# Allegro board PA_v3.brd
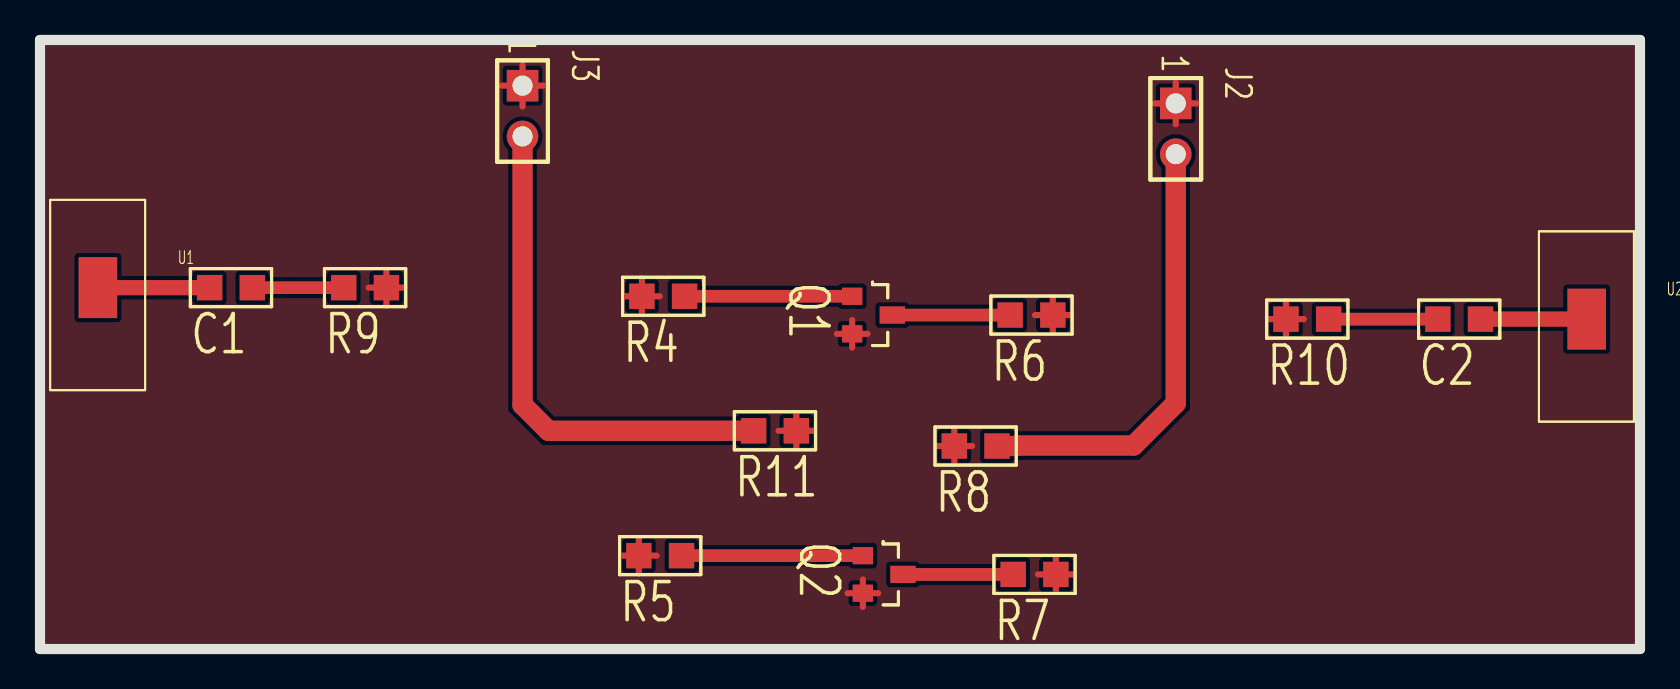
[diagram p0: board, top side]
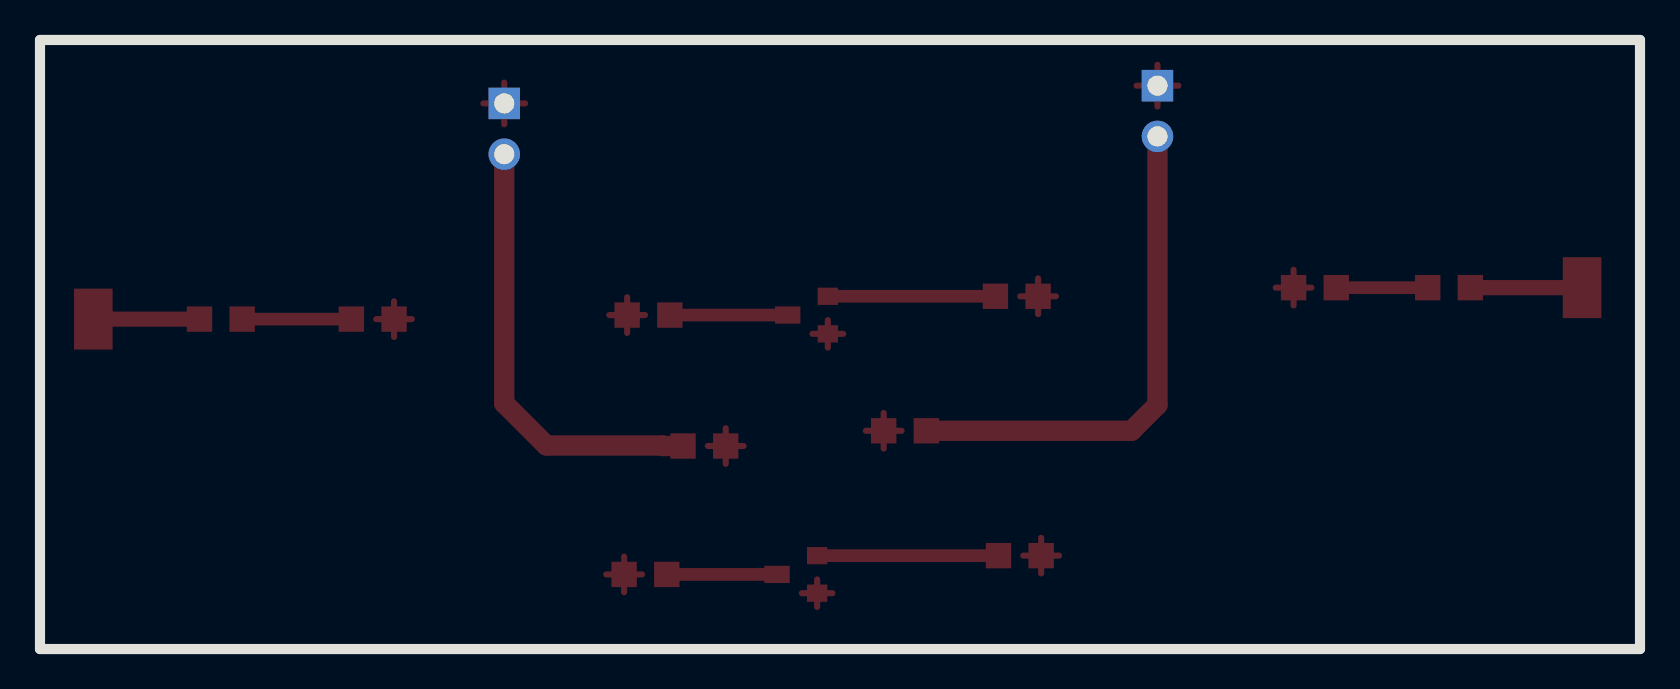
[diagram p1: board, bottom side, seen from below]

Outline 80.01 x 30.48 mm; copper layers: TOP, BOTTOM. Coordinates in mm from the lower left corner of the outline.
Outline path: 0,30.48 0,0 80.01,0 80.01,30.48 0,30.48

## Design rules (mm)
constraint set DEFAULT: min track width 0.305

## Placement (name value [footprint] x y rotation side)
C1  C NP  [SMC0805]  8.48 18.08 0 top
C2  C NP  [SMC0805]  69.9 16.51 0 top
J2  2Pin Header  [BCON_2X1V_100S_1SQ_42D]  56.79 27.31 270 top
J3  2Pin Header  [BCON_2X1V_100S_1SQ_42D]  24.13 28.19 270 top
Q1  Q2N3904  [SMSOT23BEC]  40.61 15.77 270 top
Q2  Q2N3904  [SMSOT23BEC]  41.15 2.79 270 top
R4  R small  [SMC0805]  30.1 17.65 0 top
R5  R small  [SMC0805]  29.95 4.67 0 top
R6  R small  [SMC0805]  48.51 16.71 0 top
R7  R small  [SMC0805]  48.67 3.73 0 top
R8  R small  [SMC0805]  45.72 10.16 0 top
R9  R small  [SMC0805]  15.19 18.08 0 top
R10  R small  [SMC0805]  62.31 16.51 0 top
R11  R small  [SMC0805]  35.69 10.92 0 top
U1  SMA_connector  [SMACONNECTOR]  0.51 12.95 0 top
U2  SMA_connector  [SMACONNECTOR]  74.96 11.38 0 top

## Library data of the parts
C1 C2 = C NP
J2 J3 = 2Pin Header
Q1 Q2 = Q2N3904_0
R4-R11 = R small
U1 U2 = SMA_connector

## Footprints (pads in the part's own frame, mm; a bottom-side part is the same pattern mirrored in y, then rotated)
BCON_2X1V_100S_1SQ_42D
  rect 1.575x1.575 hole 1.001: 1(0,0)
  round 1.575 hole 1.001: 2(2.54,0)
SMACONNECTOR
  rect 1.93x3.048 smd: 1(2.388,5.131)
SMC0805
  rect 1.27x1.27 smd: 1(0,0) 2(2.134,0)
SMSOT23BEC
  rect 0.864x1.016 smd: B(-1.88,0) E(0,0)
  rect 0.864x1.27 smd: C(-0.94,2.007)

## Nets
0: J2.1 J3.1 Q1.E Q2.E R4.1 R5.1 R6.2(B) R7.2(B) R8.1 R9.2(B) R10.1 R11.2(B)
N02014: J2.2 R8.2(B)
N02196: Q1.C R6.1
N02226: C1.2(B) R9.1
N02286: C2.1 R10.2(B)
N02426: Q2.B R5.2(B)
N02438: Q2.C R7.1
N02665: J3.2 R11.1
N021040: C1.1 U1.1(VIN)
N022180: C2.2(B) U2.1(VIN)
N022981: Q1.B R4.2(B)

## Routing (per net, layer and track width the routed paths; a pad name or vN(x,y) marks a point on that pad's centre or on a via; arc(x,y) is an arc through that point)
0: length 42.7
  TOP w0.305: R4.1 30.1,18.54 ; R4.1 30.1,16.76 ; R4.1 29.21,17.65 ; R4.1 30.99,17.65 ; 17.32,17.19 R9.2 ; R9.2 16.43,18.08 ; R9.2 17.32,18.98 ; R9.2 18.21,18.08 ; 36.93,10.92 R11.2 ; R11.2 37.82,10.03 ; R11.2 37.82,11.81 ; R11.2 38.71,10.92 ; 50.65,15.82 R6.2 ; R6.2 50.65,17.6 ; R6.2 51.54,16.71 ; R6.2 49.76,16.71 ; Q2.E 41.91,2.79 ; Q2.E 41.15,2.11 ; Q2.E 41.15,3.48 ; Q2.E 40.38,2.79 ; 55.75,27.31 J2.1 ; J2.1 57.84,27.31 ; J2.1 56.79,28.35 ; J2.1 56.79,26.26 ; R10.1 63.2,16.51 ; R10.1 61.41,16.51 ; R10.1 62.31,15.62 ; R10.1 62.31,17.4 ; Q1.E 41.38,15.77 ; Q1.E 39.85,15.77 ; Q1.E 40.61,16.46 ; Q1.E 40.61,15.09 ; J3.1 25.17,28.19 ; J3.1 24.13,29.24 ; J3.1 24.13,27.15 ; J3.1 23.09,28.19 ; 45.72,9.27 R8.1 ; R8.1 44.83,10.16 ; R8.1 45.72,11.05 ; R8.1 46.61,10.16 ; 29.06,4.67 R5.1 ; R5.1 29.95,3.78 ; R5.1 29.95,5.57 ; R5.1 30.84,4.67 ; 49.91,3.73 R7.2 ; R7.2 50.8,4.63 ; R7.2 51.69,3.73 ; R7.2 50.8,2.84
N02014: length 22.3
  TOP w1.016: R8.2 48.84,10.16 48.87,10.19 54.69,10.19 56.79,12.29 56.79,24.76
N02196: length 5.9
  TOP w0.635: Q1.C R6.1
N02226: length 4.6
  TOP w0.635: C1.2 R9.1
N02286: length 5.5
  TOP w0.635: R10.2 C2.1
N02426: length 9.1
  TOP w0.635: R5.2 Q2.B
N02438: length 5.5
  TOP w0.635: Q2.C R7.1
N02665: length 25.5
  TOP w1.016: J3.2 24.13,12.22 25.43,10.92 R11.1
N021040: length 5.6
  TOP w0.762: U1.1 C1.1
N022180: length 5.3
  TOP w0.762: U2.1 C2.2
N022981: length 8.4
  TOP w0.635: R4.2 40.61,17.65

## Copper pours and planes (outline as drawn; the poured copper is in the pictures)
0 on TOP: 0,30.48 0,0 80.01,0 80.01,30.48

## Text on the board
NCLEGEND-1-2: FIGURE | SIZE | 39.4 | DRILL CHART: TOP to BOTTOM | ALL UNITS ARE IN MILS | PLATED | QTY | 4
